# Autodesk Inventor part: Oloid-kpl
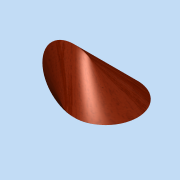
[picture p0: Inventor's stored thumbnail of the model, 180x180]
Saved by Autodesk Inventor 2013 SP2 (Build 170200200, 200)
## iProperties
Created: 2014-11
Part Number: Oloid-kpl
Material: Holz (Eiche)
Document SubType Name: Modeling
Designer: Besitzer
Density: 0.56 g/cm^3
Mass: 1706.69 g
Surface Area: 1255.28 cm^2
Volume: 3047.65 cm^3
Author: Besitzer
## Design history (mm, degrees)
sketch "Skizze1"
  geometry: L1 (-200, 0)-(0, 0); L2 (0, 0)-(0, 100); L3 (-200, 0)-(267.223, 269.752); A1 r 100 centre (0, 0) between (100, 0) and (-50, 86.603); A2 r 100 centre (0, 0) between (-50, 86.603) and (-50, 86.602); 1 further point
  constraints: 6 end point, 5 point on circle, 3 coincident, 2 centre point, 2 point on line, 1 horizontal, 1 perpendicular, 1 tangent
  dimensions: "Radius" = 100 distance of L1.end L2.end; "d6" = 200 distance of L1.start L1.end (= 2 x Radius); "d11" = 0.0001 dimension on A2 (= Zugabe)
workpoint "Arbeitspunkt1"
sketch "Skizze2"
  geometry: L1 (100, 0)-(-100, 0); L2 (-100, 0)-(144.975, 141.436); L3 (100, 0)-(100, 100); A1 r 100 centre (100, 0) between (200, 0) and (50, 86.603); A2 r 100 centre (100, 0) between (50, 86.603) and (50, 86.602); 1 further point
  constraints: 6 end point, 5 point on circle, 2 centre point, 2 coincident, 2 point on line, 1 horizontal, 1 midpoint, 1 perpendicular, 1 tangent
  dimensions: "d7" = 100 distance of L1.start L3.end (= Radius); "d9" = 100 distance from line of point (0, 0) L3 (= Radius); "d10" = 100 distance of L1.end point (0, 0) (= Radius); "d12" = 0.0001 dimension on A2 (= Zugabe)
workpoint "Arbeitspunkt2"
sketch "3D-Skizze1"
feature "Erhabene Fläche2" sketch "3D-Skizze1" dims "d19" = 0, "d20" = 90 deg, "d21" = 0, "d22" = 90 deg, "d23" = 0, "d24" = 90 deg
mirror "Spiegeln1"
feature "Fläche heften5"
mirror "Spiegeln3"
feature "Fläche heften7"
node "Volumenkörper1"
node "Fläche2"
node "Fläche3"
node "Fläche8"
node "Fläche9"
feature "Erhabene Fläche3"
feature "Fläche heften6"
other parameters: "Zugabe" = 0.0001 [user parameter; used in 2 equation terms]
